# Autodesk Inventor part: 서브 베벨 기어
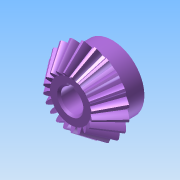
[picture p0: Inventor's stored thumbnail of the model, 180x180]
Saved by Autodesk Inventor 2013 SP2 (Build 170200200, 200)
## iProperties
Created: 2026-07
Part Number: 서브 베벨 기어
Material: Generic
Document SubType Name: Modeling
Designer: 601
Density: 1 g/cm^3
Author: 601
변환 표준: STEP AP214IS
전처리기: Build: 200, Release: 2013 SP2 Update 6 - Date: Thu 07/17/2014
전송 단위: 밀리미터
불확실성: 0.01
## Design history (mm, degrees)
node "서브 베벨기어1"
node "3D 스케치1"
body "Solid1"
node "기준1"
